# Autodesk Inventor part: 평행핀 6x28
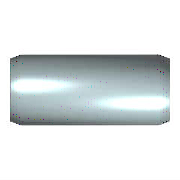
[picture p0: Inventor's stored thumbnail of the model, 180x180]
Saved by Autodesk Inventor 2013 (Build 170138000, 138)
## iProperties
Created: 2012-02
Part Number: 평행핀 6x28
Material: 스테인리스강
Description: 평행 핀
Document SubType Name: Modeling
Standard: KS B 1320
Designer: mduedu
Standards Organization: KS
Language: ko-KR
Size Designation: B 6 x  28
Categories: <MemberInstance><Categories><Category DisplayName="조임쇠" InternalName="e4da775c-781d-43d5-af7c-5136215cf5a6" Mnemonic="FSTN"><Category DisplayName="핀" InternalNa
Density: 1 g/cm^3
IsCustomPart: 1
Author: mduedu
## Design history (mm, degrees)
sketch "스케치"
  geometry: C1 r 3 at (0, 0); 1 further point
  constraints: 1 centre point, 1 coincident
  dimensions: "d1" = 6 diameter of C1 (= NND)
extrude "본체" new body sketch "스케치" distance "d2" = 28 (= NLG); taper "d3" = 0 deg
chamfer "스케치2" distance "d8" = 1.2 (= PHH); stored, may be unused: angle "d9" = 15 deg (= FAWI), second distance "d12" = 1.2 (= PHH)
node "작업 평면1"
body "Solid1"
chamfer "모따기1" distance "d4" = 1.2 (= PHH); stored, may be unused: angle "d5" = 15 deg (= FAWI), second distance "d11" = 1.2 (= PHH)
other parameters: "NND" = 6 [user parameter; used in 1 equation term], "NLG" = 28 [user parameter; used in 1 equation term], "PHH" = 1.2 [user parameter; used in 4 equation terms], "FAWI" = 15 deg [user parameter; used in 2 equation terms], "d13" = 0, "d15" = 0, "d16" = 0, "KAH" = 0.8 [user parameter]
